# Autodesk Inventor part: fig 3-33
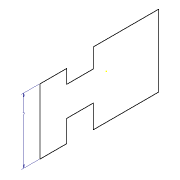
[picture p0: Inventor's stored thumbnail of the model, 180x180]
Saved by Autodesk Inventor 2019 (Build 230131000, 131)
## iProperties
Created: 2018-03
Part Number: fig 3-33
Material: Generic
Document SubType Name: Modeling
Designer: CADCIM 00
Density: 1 g/cm^3
Appearance: Default
Author: CADCIM 00
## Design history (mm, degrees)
sketch "Sketch1"
  geometry: L1 (-4.566, 7.164)-(2.434, 7.164); L2 (2.434, 7.164)-(2.434, 4.293); L3 (2.434, 4.293)-(0.957, 4.293); L4 (0.957, 4.293)-(0.957, 1.422); L5 (0.957, 1.422)-(3.008, 1.422); L6 (3.008, 1.422)-(3.008, -5.605); L7 (3.008, -5.605)-(-4.703, -5.605); L8 (-4.703, -5.605)-(-4.703, 1.422); L9 (-4.703, 1.422)-(-2.215, 1.422); L10 (-2.215, 1.422)-(-2.215, 4.293); L11 (-2.215, 4.293)-(-4.566, 4.293); L12 (-4.566, 4.293)-(-4.566, 7.164); 1 further point
  constraints: 24 end point, 9 perpendicular, 4 point on line, 1 horizontal
  dimensions: "d0" = 7 distance of L1.start L1.end
